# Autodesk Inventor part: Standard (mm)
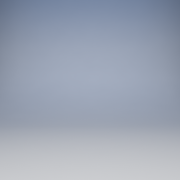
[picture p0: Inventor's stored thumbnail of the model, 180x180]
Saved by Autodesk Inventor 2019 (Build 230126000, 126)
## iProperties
Created: 2018-02
Part Number: Standard (mm)
Material: Všeobecné
Document SubType Name: Modeling
Density: 1 g/cm^3
Appearance: Výchozí
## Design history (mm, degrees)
